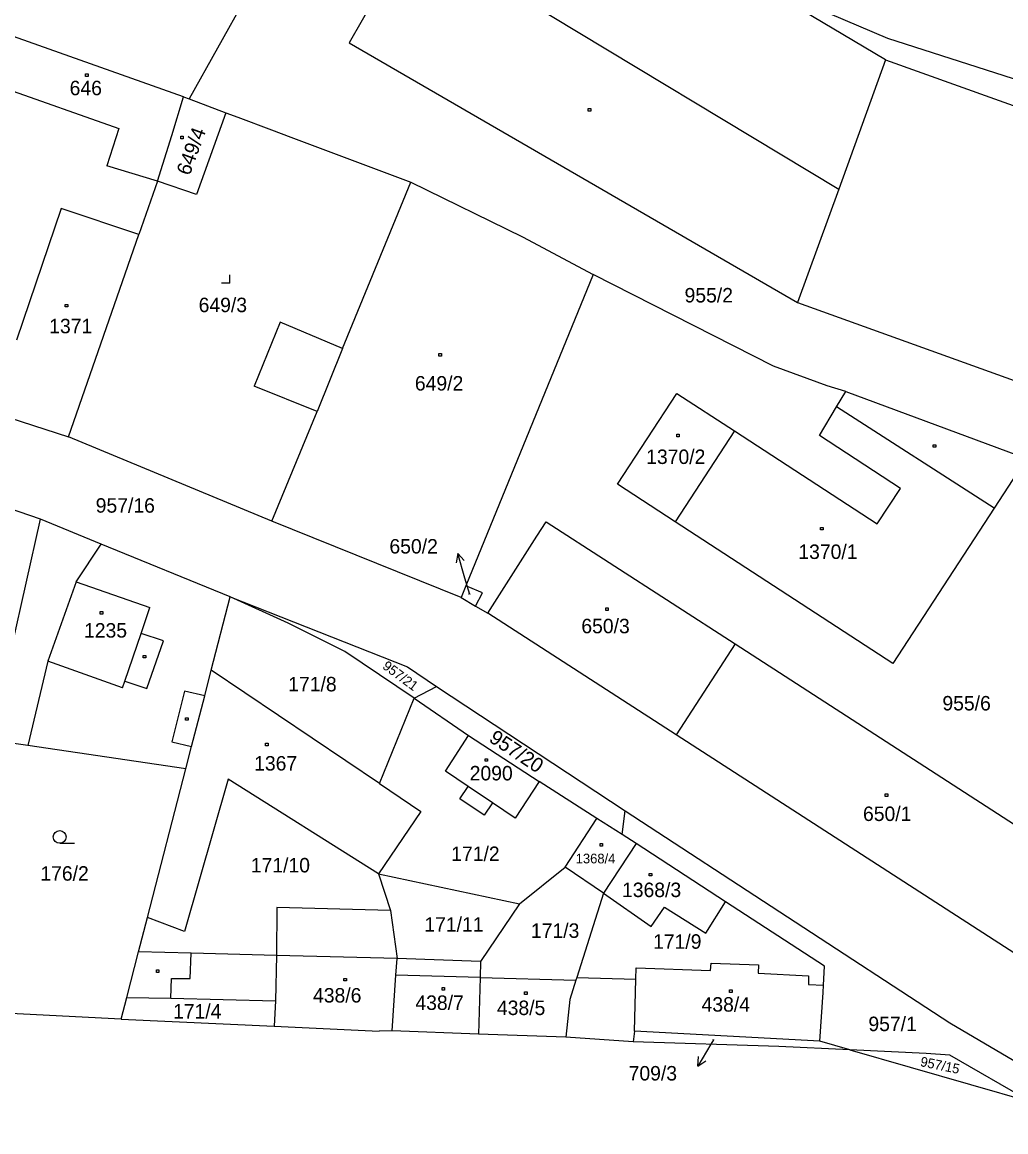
# Model space of a CAD drawing. Extents: x -711879 to -711361, y -1048782 to -1048177.
# Drawn here: x -711762.1 to -711646.6, y -1048413.5 to -1048283.1 of the extents above; entities that cross this region are included whole.
import ezdxf

# ---------------------------------------------------------------- set-up
doc = ezdxf.new("R2010")
doc.units = 0
for name, color, linetype in [('Vrstva 1', 7, 'Continuous'), ('Vrstva 13', 7, 'Continuous'), ('Vrstva 14', 7, 'Continuous'), ('Vrstva 15', 7, 'Continuous'), ('Vrstva 16', 7, 'Continuous'), ('Vrstva 2', 7, 'Continuous'), ('Vrstva 23', 7, 'Continuous'), ('Vrstva 25', 7, 'Continuous'), ('Vrstva 46', 7, 'Continuous')]:
    doc.layers.add(name, color=color, linetype=linetype)

msp = doc.modelspace()

# ---------------------------------------------------------------- linework, layer by layer
at = {"layer": 'Vrstva 1'}
for p, q in [((-711727.66, -1048265.49), (-711742.5, -1048292.14)), ((-711716.27, -1048272.51), (-711723.71, -1048285.54)), ((-711667.27, -1048282.09), (-711660.45, -1048284.99)), ((-711743.18, -1048291.89), (-711767.16, -1048283.42)), ((-711723.71, -1048285.54), (-711671.04, -1048316.08)), ((-711660.45, -1048284.99), (-711642.81, -1048290.69)), ((-711744.57, -1048296.45), (-711743.18, -1048291.89)), ((-711743.18, -1048291.89), (-711742.5, -1048292.14)), ((-711742.5, -1048292.14), (-711738.21, -1048293.76)), ((-711738.21, -1048293.76), (-711741.66, -1048303.38)), ((-711738.21, -1048293.76), (-711736.78, -1048294.29)), ((-711736.78, -1048294.29), (-711732.82, -1048295.79)), ((-711732.82, -1048295.79), (-711730.55, -1048296.64)), ((-711746.25, -1048301.79), (-711744.57, -1048296.45)), ((-711730.55, -1048296.64), (-711716.48, -1048301.93)), ((-711746.25, -1048301.79), (-711748.44, -1048308.08)), ((-711741.66, -1048303.38), (-711746.25, -1048301.79)), ((-711724.49, -1048321.46), (-711716.48, -1048301.93)), ((-711716.48, -1048301.93), (-711703.35, -1048308.35)), ((-711757.54, -1048305.01), (-711762.79, -1048320.49)), ((-711748.44, -1048308.08), (-711757.54, -1048305.01)), ((-711756.7, -1048331.86), (-711748.44, -1048308.08)), ((-711703.35, -1048308.35), (-711695.03, -1048312.79)), ((-711695.03, -1048312.79), (-711710, -1048349.36)), ((-711673.85, -1048323.54), (-711695.03, -1048312.79)), ((-711671.04, -1048316.08), (-711614.15, -1048336.53)), ((-711731.82, -1048318.39), (-711734.88, -1048325.91)), ((-711724.49, -1048321.46), (-711731.82, -1048318.39)), ((-711667.55, -1048325.84), (-711673.85, -1048323.54)), ((-711727.49, -1048328.88), (-711734.88, -1048325.91)), ((-711665.35, -1048326.54), (-711667.55, -1048325.84)), ((-711692.18, -1048337.41), (-711685.2, -1048326.74)), ((-711685.2, -1048326.74), (-711678.42, -1048331.16)), ((-711666.44, -1048328.34), (-711665.35, -1048326.54)), ((-711665.35, -1048326.54), (-711644.11, -1048334.41)), ((-711668.46, -1048331.69), (-711666.44, -1048328.34)), ((-711765.69, -1048328.92), (-711756.7, -1048331.86)), ((-711732.79, -1048341.75), (-711727.49, -1048328.88)), ((-711678.42, -1048331.16), (-711685.4, -1048341.84)), ((-711678.42, -1048331.16), (-711661.65, -1048342.08)), ((-711732.79, -1048341.75), (-711756.7, -1048331.86)), ((-711658.93, -1048337.91), (-711668.46, -1048331.69)), ((-711759.97, -1048341.54), (-711780.84, -1048334.37)), ((-711644.11, -1048334.41), (-711647.9, -1048340.23)), ((-711685.4, -1048341.84), (-711692.18, -1048337.41)), ((-711661.65, -1048342.08), (-711658.93, -1048337.91)), ((-711647.9, -1048340.23), (-711659.83, -1048358.5)), ((-711765.82, -1048367.48), (-711759.97, -1048341.54)), ((-711752.85, -1048344.45), (-711759.97, -1048341.54)), ((-711710.56, -1048350.72), (-711732.79, -1048341.75)), ((-711701.66, -1048343.53), (-711700.58, -1048341.84)), ((-711700.58, -1048341.84), (-711678.36, -1048356.19)), ((-711659.83, -1048358.5), (-711685.4, -1048341.84)), ((-711707.43, -1048352.57), (-711701.66, -1048343.53)), ((-711755.78, -1048348.87), (-711752.85, -1048344.45)), ((-711737.69, -1048350.65), (-711752.85, -1048344.45)), ((-711755.78, -1048348.87), (-711759.13, -1048358.21)), ((-711710, -1048349.36), (-711710.56, -1048350.72)), ((-711708.51, -1048349.99), (-711710, -1048349.36)), ((-711739.91, -1048359.26), (-711737.69, -1048350.65)), ((-711730.89, -1048353.75), (-711737.69, -1048350.65)), ((-711737.69, -1048350.65), (-711716.85, -1048358.87)), ((-711710.56, -1048350.72), (-711708.85, -1048351.73)), ((-711708.85, -1048351.73), (-711708.05, -1048350.19)), ((-711708.05, -1048350.19), (-711708.51, -1048349.99)), ((-711708.85, -1048351.73), (-711707.43, -1048352.57)), ((-711685.27, -1048366.88), (-711707.43, -1048352.57)), ((-711724.23, -1048357.09), (-711730.89, -1048353.75)), ((-711716.07, -1048362.54), (-711724.23, -1048357.09)), ((-711678.36, -1048356.19), (-711685.27, -1048366.88)), ((-711678.36, -1048356.19), (-711645.51, -1048377.4)), ((-711759.13, -1048358.21), (-711761.48, -1048368.12)), ((-711740.69, -1048362.28), (-711739.91, -1048359.26)), ((-711720.15, -1048372.57), (-711739.91, -1048359.26)), ((-711716.85, -1048358.87), (-711713.43, -1048361.18)), ((-711742.23, -1048368.24), (-711740.69, -1048362.28)), ((-711716.07, -1048362.54), (-711713.43, -1048361.18)), ((-711713.43, -1048361.18), (-711691.26, -1048375.79)), ((-711720.15, -1048372.57), (-711716.07, -1048362.54)), ((-711716.07, -1048362.54), (-711709.69, -1048366.95)), ((-711712.41, -1048371.15), (-711709.69, -1048366.95)), ((-711709.69, -1048366.95), (-711701.4, -1048372.33)), ((-711643.01, -1048394.17), (-711685.27, -1048366.88)), ((-711742.9, -1048370.85), (-711761.48, -1048368.12)), ((-711742.9, -1048370.85), (-711742.23, -1048368.24)), ((-711747.41, -1048388.32), (-711742.9, -1048370.85)), ((-711709.74, -1048372.93), (-711712.41, -1048371.15)), ((-711737.93, -1048372.06), (-711743.07, -1048389.96)), ((-711720.28, -1048383.18), (-711737.93, -1048372.06)), ((-711720.15, -1048372.57), (-711715.28, -1048375.87)), ((-711701.4, -1048372.33), (-711704.2, -1048376.64)), ((-711694.62, -1048376.68), (-711701.4, -1048372.33)), ((-711710.72, -1048374.4), (-711709.74, -1048372.93)), ((-711707.85, -1048376.32), (-711710.72, -1048374.4)), ((-711706.87, -1048374.86), (-711707.85, -1048376.32)), ((-711704.2, -1048376.64), (-711706.87, -1048374.86)), ((-711715.28, -1048375.87), (-711720.28, -1048383.18)), ((-711698.33, -1048382.41), (-711694.62, -1048376.68)), ((-711691.65, -1048378.56), (-711694.62, -1048376.68)), ((-711691.65, -1048378.56), (-711691.26, -1048375.79)), ((-711691.26, -1048375.79), (-711653.14, -1048400.7)), ((-711690, -1048379.64), (-711691.65, -1048378.56)), ((-711690, -1048379.64), (-711693.83, -1048385.47)), ((-711679.47, -1048386.49), (-711690, -1048379.64)), ((-711720.28, -1048383.18), (-711718.87, -1048387.5)), ((-711720.28, -1048383.18), (-711703.7, -1048386.71)), ((-711703.7, -1048386.71), (-711698.33, -1048382.41)), ((-711693.83, -1048385.47), (-711698.33, -1048382.41)), ((-711693.83, -1048385.47), (-711696.97, -1048395.37)), ((-711693.83, -1048385.47), (-711688.22, -1048389.38)), ((-711732.2, -1048387.16), (-711732.26, -1048392.78)), ((-711718.87, -1048387.5), (-711732.2, -1048387.16)), ((-711703.7, -1048386.71), (-711708.26, -1048393.5)), ((-711688.22, -1048389.38), (-711686.64, -1048387.11)), ((-711686.64, -1048387.11), (-711681.79, -1048390.17)), ((-711681.79, -1048390.17), (-711679.47, -1048386.49)), ((-711667.85, -1048394.05), (-711679.47, -1048386.49)), ((-711748.45, -1048392.36), (-711747.41, -1048388.32)), ((-711743.07, -1048389.96), (-711747.41, -1048388.32)), ((-711718.87, -1048387.5), (-711718.09, -1048393.15)), ((-711749.84, -1048397.74), (-711748.45, -1048392.36)), ((-711742.26, -1048392.52), (-711748.45, -1048392.36)), ((-711732.26, -1048392.78), (-711742.26, -1048392.52)), ((-711718.22, -1048395.1), (-711718.09, -1048393.15)), ((-711708.26, -1048393.5), (-711718.09, -1048393.15)), ((-711708.26, -1048393.5), (-711708.32, -1048395.39)), ((-711681.24, -1048394.54), (-711681.17, -1048393.71)), ((-711681.17, -1048393.71), (-711675.63, -1048393.88)), ((-711690.04, -1048395.57), (-711689.98, -1048394.24)), ((-711689.98, -1048394.24), (-711681.24, -1048394.54)), ((-711675.63, -1048393.88), (-711675.67, -1048394.85)), ((-711675.67, -1048394.85), (-711669.75, -1048395.19)), ((-711667.96, -1048396.27), (-711667.85, -1048394.05)), ((-711718.64, -1048401.64), (-711718.22, -1048395.1)), ((-711708.32, -1048395.39), (-711708.51, -1048402.02)), ((-711708.32, -1048395.39), (-711697.08, -1048395.71)), ((-711697.08, -1048395.71), (-711697.79, -1048397.95)), ((-711696.97, -1048395.37), (-711697.08, -1048395.71)), ((-711696.97, -1048395.37), (-711690.04, -1048395.57)), ((-711669.75, -1048395.19), (-711669.72, -1048396.22)), ((-711669.72, -1048396.22), (-711667.96, -1048396.27)), ((-711668, -1048397.13), (-711667.96, -1048396.27)), ((-711668.42, -1048402.85), (-711668, -1048397.13)), ((-711750.5, -1048400.29), (-711749.84, -1048397.74)), ((-711749.84, -1048397.74), (-711744.65, -1048397.8)), ((-711744.65, -1048397.8), (-711732.36, -1048398.12)), ((-711732.36, -1048398.12), (-711732.53, -1048401.08)), ((-711697.79, -1048397.95), (-711698.25, -1048402.4)), ((-711750.5, -1048400.29), (-711772.94, -1048399.09)), ((-711750.5, -1048400.29), (-711732.53, -1048401.08)), ((-711732.53, -1048401.08), (-711720.2, -1048401.7)), ((-711653.14, -1048400.7), (-711631.45, -1048413.51)), ((-711718.64, -1048401.64), (-711720.2, -1048401.7)), ((-711708.51, -1048402.02), (-711718.64, -1048401.64)), ((-711698.25, -1048402.4), (-711708.51, -1048402.02)), ((-711690.33, -1048402.94), (-711698.25, -1048402.4)), ((-711690.18, -1048401.69), (-711690.33, -1048402.94)), ((-711668.42, -1048402.85), (-711690.18, -1048401.69)), ((-711664.88, -1048403.87), (-711668.42, -1048402.85)), ((-711673.24, -1048403.48), (-711690.33, -1048402.94)), ((-711664.88, -1048403.87), (-711673.24, -1048403.48)), ((-711664.88, -1048403.87), (-711643.62, -1048410)), ((-711655.9, -1048404.29), (-711664.88, -1048403.87)), ((-711653.11, -1048404.49), (-711655.9, -1048404.29)), ((-711643.62, -1048410), (-711653.11, -1048404.49))]:
    msp.add_line(p, q, dxfattribs=at)
at = {"layer": 'Vrstva 13'}
for p, q in [((-711709.54, -1048350.38), (-711710.11, -1048348.44)), ((-711680.9, -1048402.69), (-711681.21, -1048403.21))]:
    msp.add_line(p, q, dxfattribs=at)
at = {"layer": 'Vrstva 16'}
for p, q in [((-711710.952, -1048345.56), (-711711.151, -1048346.66)), ((-711710.11, -1048348.44), (-711710.952, -1048345.56)), ((-711710.952, -1048345.56), (-711710.191, -1048346.38)), ((-711681.21, -1048403.21), (-711682.757, -1048405.78)), ((-711682.757, -1048405.78), (-711682.669, -1048404.665)), ((-711682.757, -1048405.78), (-711681.813, -1048405.181))]:
    msp.add_line(p, q, dxfattribs=at)
at = {"layer": 'Vrstva 2'}
for p, q in [((-711660.67, -1048287.56), (-711713.35, -1048256.2)), ((-711716.27, -1048272.51), (-711666.19, -1048302.74)), ((-711660.67, -1048287.56), (-711666.19, -1048302.74)), ((-711660.67, -1048287.56), (-711603.88, -1048307.87)), ((-711764.53, -1048290.75), (-711750.79, -1048295.62)), ((-711750.79, -1048295.62), (-711752.2, -1048300.02)), ((-711746.25, -1048301.79), (-711752.2, -1048300.02)), ((-711666.19, -1048302.74), (-711671.04, -1048316.08)), ((-711724.49, -1048321.46), (-711727.49, -1048328.88)), ((-711647.9, -1048340.23), (-711666.44, -1048328.34)), ((-711755.78, -1048348.87), (-711747.14, -1048351.9)), ((-711748.17, -1048354.95), (-711747.14, -1048351.9)), ((-711750.07, -1048360.57), (-711748.17, -1048354.95)), ((-711745.54, -1048355.83), (-711748.17, -1048354.95)), ((-711747.47, -1048361.43), (-711745.54, -1048355.83)), ((-711750.34, -1048361.36), (-711759.13, -1048358.21)), ((-711750.34, -1048361.36), (-711750.07, -1048360.57)), ((-711750.07, -1048360.57), (-711747.47, -1048361.43)), ((-711743.07, -1048361.74), (-711744.57, -1048367.68)), ((-711740.69, -1048362.28), (-711743.07, -1048361.74)), ((-711761.48, -1048368.12), (-711765.82, -1048367.48)), ((-711744.57, -1048367.68), (-711742.23, -1048368.24)), ((-711706.87, -1048374.86), (-711709.74, -1048372.93)), ((-711742.39, -1048395.51), (-711742.26, -1048392.52)), ((-711732.26, -1048392.78), (-711732.36, -1048398.12)), ((-711718.09, -1048393.15), (-711732.26, -1048392.78)), ((-711744.65, -1048397.8), (-711744.6, -1048395.49)), ((-711744.6, -1048395.49), (-711742.39, -1048395.51)), ((-711708.32, -1048395.39), (-711718.22, -1048395.1)), ((-711690.18, -1048401.69), (-711690.04, -1048395.57))]:
    msp.add_line(p, q, dxfattribs=at)
at = {"layer": 'Vrstva 23'}
for p, q in [((-711737.73, -1048313.8), (-711737.73, -1048312.8)), ((-711737.73, -1048313.8), (-711738.73, -1048313.8)), ((-711757.73, -1048379.61), (-711755.98, -1048379.61))]:
    msp.add_line(p, q, dxfattribs=at)
msp.add_circle((-711757.73, -1048378.86), 0.75, dxfattribs=at)
at = {"layer": 'Vrstva 25'}
for p, q in [((-711754.69, -1048289.21), (-711754.39, -1048289.21)), ((-711754.69, -1048289.51), (-711754.69, -1048289.21)), ((-711754.39, -1048289.21), (-711754.39, -1048289.51)), ((-711754.39, -1048289.51), (-711754.69, -1048289.51)), ((-711695.63, -1048293.28), (-711695.33, -1048293.28)), ((-711695.63, -1048293.58), (-711695.63, -1048293.28)), ((-711695.33, -1048293.28), (-711695.33, -1048293.58)), ((-711695.33, -1048293.58), (-711695.63, -1048293.58)), ((-711743.5, -1048296.53), (-711743.2, -1048296.53)), ((-711743.5, -1048296.83), (-711743.5, -1048296.53)), ((-711743.2, -1048296.83), (-711743.5, -1048296.83)), ((-711743.2, -1048296.53), (-711743.2, -1048296.83)), ((-711757.08, -1048316.29), (-711756.78, -1048316.29)), ((-711757.08, -1048316.59), (-711757.08, -1048316.29)), ((-711756.78, -1048316.59), (-711757.08, -1048316.59)), ((-711756.78, -1048316.29), (-711756.78, -1048316.59)), ((-711713.17, -1048322.07), (-711712.87, -1048322.07)), ((-711713.17, -1048322.37), (-711713.17, -1048322.07)), ((-711712.87, -1048322.37), (-711713.17, -1048322.37)), ((-711712.87, -1048322.07), (-711712.87, -1048322.37)), ((-711685.22, -1048331.54), (-711684.92, -1048331.54)), ((-711685.22, -1048331.84), (-711685.22, -1048331.54)), ((-711684.92, -1048331.84), (-711685.22, -1048331.84)), ((-711684.92, -1048331.54), (-711684.92, -1048331.84)), ((-711655.08, -1048332.77), (-711654.78, -1048332.77)), ((-711655.08, -1048333.07), (-711655.08, -1048332.77)), ((-711654.78, -1048333.07), (-711655.08, -1048333.07)), ((-711654.78, -1048332.77), (-711654.78, -1048333.07)), ((-711668.31, -1048342.49), (-711668.01, -1048342.49)), ((-711668.31, -1048342.79), (-711668.31, -1048342.49)), ((-711668.01, -1048342.79), (-711668.31, -1048342.79)), ((-711668.01, -1048342.49), (-711668.01, -1048342.79)), ((-711693.57, -1048351.96), (-711693.27, -1048351.96)), ((-711693.57, -1048352.26), (-711693.57, -1048351.96)), ((-711693.27, -1048351.96), (-711693.27, -1048352.26)), ((-711752.97, -1048352.38), (-711752.67, -1048352.38)), ((-711752.97, -1048352.68), (-711752.97, -1048352.38)), ((-711752.67, -1048352.68), (-711752.97, -1048352.68)), ((-711752.67, -1048352.38), (-711752.67, -1048352.68)), ((-711693.27, -1048352.26), (-711693.57, -1048352.26)), ((-711747.91, -1048357.53), (-711747.61, -1048357.53)), ((-711747.91, -1048357.83), (-711747.91, -1048357.53)), ((-711747.61, -1048357.83), (-711747.91, -1048357.83)), ((-711747.61, -1048357.53), (-711747.61, -1048357.83)), ((-711742.93, -1048364.86), (-711742.63, -1048364.86)), ((-711742.93, -1048365.16), (-711742.93, -1048364.86)), ((-711742.63, -1048364.86), (-711742.63, -1048365.16)), ((-711742.63, -1048365.16), (-711742.93, -1048365.16)), ((-711733.53, -1048367.86), (-711733.23, -1048367.86)), ((-711733.53, -1048368.16), (-711733.53, -1048367.86)), ((-711733.23, -1048368.16), (-711733.53, -1048368.16)), ((-711733.23, -1048367.86), (-711733.23, -1048368.16)), ((-711707.75, -1048369.67), (-711707.45, -1048369.67)), ((-711707.75, -1048369.97), (-711707.75, -1048369.67)), ((-711707.45, -1048369.97), (-711707.75, -1048369.97)), ((-711707.45, -1048369.67), (-711707.45, -1048369.97)), ((-711660.72, -1048373.81), (-711660.42, -1048373.81)), ((-711660.72, -1048374.11), (-711660.72, -1048373.81)), ((-711660.42, -1048374.11), (-711660.72, -1048374.11)), ((-711660.42, -1048373.81), (-711660.42, -1048374.11)), ((-711694.23, -1048379.63), (-711693.93, -1048379.63)), ((-711694.23, -1048379.93), (-711694.23, -1048379.63)), ((-711693.93, -1048379.93), (-711694.23, -1048379.93)), ((-711693.93, -1048379.63), (-711693.93, -1048379.93)), ((-711688.46, -1048383.15), (-711688.16, -1048383.15)), ((-711688.46, -1048383.45), (-711688.46, -1048383.15)), ((-711688.16, -1048383.15), (-711688.16, -1048383.45)), ((-711688.16, -1048383.45), (-711688.46, -1048383.45)), ((-711746.37, -1048394.48), (-711746.07, -1048394.48)), ((-711746.37, -1048394.78), (-711746.37, -1048394.48)), ((-711746.07, -1048394.78), (-711746.37, -1048394.78)), ((-711746.07, -1048394.48), (-711746.07, -1048394.78)), ((-711724.32, -1048395.48), (-711724.02, -1048395.48)), ((-711724.32, -1048395.78), (-711724.32, -1048395.48)), ((-711724.02, -1048395.78), (-711724.32, -1048395.78)), ((-711724.02, -1048395.48), (-711724.02, -1048395.78)), ((-711712.8, -1048396.56), (-711712.5, -1048396.56)), ((-711712.8, -1048396.86), (-711712.8, -1048396.56)), ((-711712.5, -1048396.86), (-711712.8, -1048396.86)), ((-711712.5, -1048396.56), (-711712.5, -1048396.86)), ((-711703.11, -1048397.07), (-711702.81, -1048397.07)), ((-711703.11, -1048397.37), (-711703.11, -1048397.07)), ((-711702.81, -1048397.37), (-711703.11, -1048397.37)), ((-711702.81, -1048397.07), (-711702.81, -1048397.37)), ((-711679, -1048396.84), (-711678.7, -1048396.84)), ((-711679, -1048397.14), (-711679, -1048396.84)), ((-711678.7, -1048397.14), (-711679, -1048397.14)), ((-711678.7, -1048396.84), (-711678.7, -1048397.14))]:
    msp.add_line(p, q, dxfattribs=at)
at = {"layer": 'Vrstva 46'}
for p, q in [((-711723.71, -1048285.54), (-711723.71, -1048285.54)), ((-711660.67, -1048287.56), (-711660.67, -1048287.56)), ((-711743.18, -1048291.89), (-711743.18, -1048291.89)), ((-711742.5, -1048292.14), (-711742.5, -1048292.14)), ((-711738.21, -1048293.76), (-711738.21, -1048293.76)), ((-711736.78, -1048294.29), (-711736.78, -1048294.29)), ((-711732.82, -1048295.79), (-711732.82, -1048295.79)), ((-711744.57, -1048296.45), (-711744.57, -1048296.45)), ((-711730.55, -1048296.64), (-711730.55, -1048296.64)), ((-711752.2, -1048300.02), (-711752.2, -1048300.02)), ((-711746.25, -1048301.79), (-711746.25, -1048301.79)), ((-711716.48, -1048301.93), (-711716.48, -1048301.93)), ((-711748.44, -1048308.08), (-711748.44, -1048308.08)), ((-711703.35, -1048308.35), (-711703.35, -1048308.35)), ((-711695.03, -1048312.79), (-711695.03, -1048312.79)), ((-711671.04, -1048316.08), (-711671.04, -1048316.08)), ((-711731.82, -1048318.39), (-711731.82, -1048318.39)), ((-711724.49, -1048321.46), (-711724.49, -1048321.46)), ((-711673.85, -1048323.54), (-711673.85, -1048323.54)), ((-711734.88, -1048325.91), (-711734.88, -1048325.91)), ((-711667.55, -1048325.84), (-711667.55, -1048325.84)), ((-711685.2, -1048326.74), (-711685.2, -1048326.74)), ((-711665.35, -1048326.54), (-711665.35, -1048326.54)), ((-711666.44, -1048328.34), (-711666.44, -1048328.34)), ((-711727.49, -1048328.88), (-711727.49, -1048328.88)), ((-711678.42, -1048331.16), (-711678.42, -1048331.16)), ((-711756.7, -1048331.86), (-711756.7, -1048331.86)), ((-711668.46, -1048331.69), (-711668.46, -1048331.69)), ((-711692.18, -1048337.41), (-711692.18, -1048337.41)), ((-711658.93, -1048337.91), (-711658.93, -1048337.91)), ((-711647.9, -1048340.23), (-711647.9, -1048340.23)), ((-711759.97, -1048341.54), (-711759.97, -1048341.54)), ((-711732.79, -1048341.75), (-711732.79, -1048341.75)), ((-711700.58, -1048341.84), (-711700.58, -1048341.84)), ((-711685.4, -1048341.84), (-711685.4, -1048341.84)), ((-711661.65, -1048342.08), (-711661.65, -1048342.08)), ((-711701.66, -1048343.53), (-711701.66, -1048343.53)), ((-711755.78, -1048348.87), (-711755.78, -1048348.87)), ((-711710, -1048349.36), (-711710, -1048349.36)), ((-711737.69, -1048350.65), (-711737.69, -1048350.65)), ((-711710.56, -1048350.72), (-711710.56, -1048350.72)), ((-711708.51, -1048349.99), (-711708.51, -1048349.99)), ((-711747.14, -1048351.9), (-711747.14, -1048351.9)), ((-711708.85, -1048351.73), (-711708.85, -1048351.73)), ((-711707.43, -1048352.57), (-711707.43, -1048352.57)), ((-711730.89, -1048353.75), (-711730.89, -1048353.75)), ((-711724.23, -1048357.09), (-711724.23, -1048357.09)), ((-711678.36, -1048356.19), (-711678.36, -1048356.19)), ((-711759.13, -1048358.21), (-711759.13, -1048358.21)), ((-711659.83, -1048358.5), (-711659.83, -1048358.5)), ((-711716.07, -1048362.54), (-711716.07, -1048362.54)), ((-711709.69, -1048366.95), (-711709.69, -1048366.95)), ((-711685.27, -1048366.88), (-711685.27, -1048366.88)), ((-711742.9, -1048370.85), (-711742.9, -1048370.85)), ((-711712.41, -1048371.15), (-711712.41, -1048371.15)), ((-711720.15, -1048372.57), (-711720.15, -1048372.57)), ((-711701.4, -1048372.33), (-711701.4, -1048372.33)), ((-711709.74, -1048372.93), (-711709.74, -1048372.93)), ((-711706.87, -1048374.86), (-711706.87, -1048374.86)), ((-711704.2, -1048376.64), (-711704.2, -1048376.64)), ((-711691.65, -1048378.56), (-711691.65, -1048378.56)), ((-711690, -1048379.64), (-711690, -1048379.64)), ((-711720.28, -1048383.18), (-711720.28, -1048383.18)), ((-711693.83, -1048385.47), (-711693.83, -1048385.47)), ((-711703.7, -1048386.71), (-711703.7, -1048386.71)), ((-711718.87, -1048387.5), (-711718.87, -1048387.5)), ((-711718.09, -1048393.15), (-711718.09, -1048393.15)), ((-711708.26, -1048393.5), (-711708.26, -1048393.5)), ((-711689.98, -1048394.24), (-711689.98, -1048394.24)), ((-711667.85, -1048394.05), (-711667.85, -1048394.05)), ((-711708.32, -1048395.39), (-711708.32, -1048395.39)), ((-711697.08, -1048395.71), (-711697.08, -1048395.71)), ((-711668, -1048397.13), (-711668, -1048397.13)), ((-711749.84, -1048397.74), (-711749.84, -1048397.74)), ((-711744.65, -1048397.8), (-711744.65, -1048397.8)), ((-711732.36, -1048398.12), (-711732.36, -1048398.12)), ((-711697.79, -1048397.95), (-711697.79, -1048397.95)), ((-711750.5, -1048400.29), (-711750.5, -1048400.29)), ((-711732.53, -1048401.08), (-711732.53, -1048401.08)), ((-711720.2, -1048401.7), (-711720.2, -1048401.7)), ((-711718.64, -1048401.64), (-711718.64, -1048401.64)), ((-711698.25, -1048402.4), (-711698.25, -1048402.4)), ((-711668.42, -1048402.85), (-711668.42, -1048402.85)), ((-711690.33, -1048402.94), (-711690.33, -1048402.94)), ((-711664.88, -1048403.87), (-711664.88, -1048403.87)), ((-711655.9, -1048404.29), (-711655.9, -1048404.29)), ((-711653.11, -1048404.49), (-711653.11, -1048404.49))]:
    msp.add_line(p, q, dxfattribs=at)

# ---------------------------------------------------------------- texts
at = {"layer": 'Vrstva 14'}
for s, height, p in [('955/2', 1.7, (-711684.3, -1048316.06)), ('957/16', 1.7, (-711753.496, -1048340.76)), ('171/8', 1.7, (-711730.87, -1048361.76)), ('955/6', 1.7, (-711654, -1048364)), ('171/2', 1.7, (-711711.72, -1048381.69)), ('171/10', 1.7, (-711735.27, -1048383.03)), ('176/2', 1.7, (-711760, -1048384)), ('171/11', 1.7, (-711714.88, -1048390)), ('171/3', 1.7, (-711702.35, -1048390.72)), ('171/9', 1.7, (-711688, -1048392)), ('171/4', 1.7, (-711744.41, -1048400.2)), ('957/1', 1.7, (-711662.696, -1048401.68)), ('709/3', 0.1, (-711681.109, -1048402.69))]:
    msp.add_text(s, height=height, dxfattribs=at).set_placement(p)
for s, height, rotation, p in [('957/21', 1.14, 323.39889, (-711719.894, -1048358.99)), ('957/20', 1.7, 326.4246, (-711707.402, -1048367.585)), ('957/15', 1.14, 348.47667, (-711656.672, -1048405.779))]:
    msp.add_text(s, height=height, rotation=rotation, dxfattribs=at).set_placement(p)
at = {"layer": 'Vrstva 15'}
for s, height, p in [('646', 1.7, (-711756.56, -1048291.71)), ('649/3', 1.7, (-711741.4, -1048317.2)), ('1371', 1.7, (-711758.96, -1048319.68)), ('649/2', 1.7, (-711715.99, -1048326.41)), ('1370/2', 1.7, (-711688.81, -1048335.04)), ('1370/1', 1.7, (-711670.93, -1048346.2)), ('650/2', 0.1, (-711709.746, -1048350.38)), ('650/3', 1.7, (-711696.43, -1048354.93)), ('1235', 1.7, (-711754.87, -1048355.44)), ('1367', 1.7, (-711734.88, -1048371.06)), ('2090', 1.7, (-711709.55, -1048372.22)), ('650/1', 1.7, (-711663.33, -1048376.99)), ('1368/4', 1.14, (-711697.091, -1048381.97)), ('1368/3', 1.7, (-711691.65, -1048385.93)), ('438/6', 1.7, (-711727.96, -1048398.32)), ('438/7', 1.7, (-711715.93, -1048399.19)), ('438/4', 1.7, (-711682.3, -1048399.39)), ('438/5', 1.7, (-711706.35, -1048399.79))]:
    msp.add_text(s, height=height, dxfattribs=at).set_placement(p)
msp.add_text('649/4', height=1.7, rotation=70.01685, dxfattribs=at).set_placement((-711742.46, -1048301.24))
at = {"layer": 'Vrstva 16'}
for s, p in [('650/2', (-711718.981, -1048345.56)), ('709/3', (-711690.872, -1048407.48))]:
    msp.add_text(s, height=1.7, dxfattribs=at).set_placement(p)

doc.saveas('drawing.dxf')
